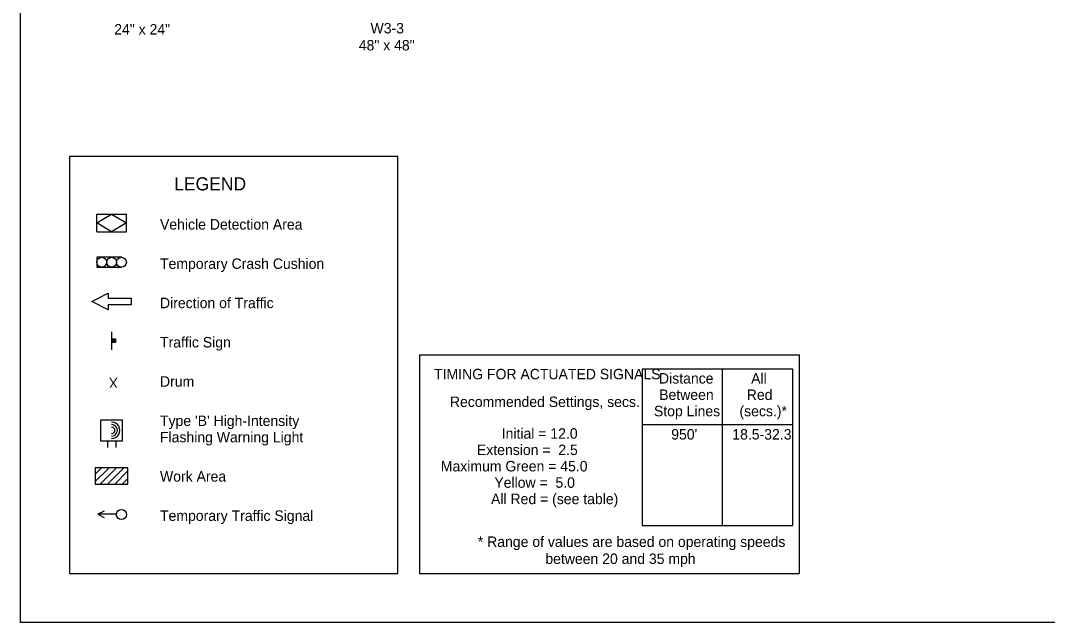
# Model space of a CAD drawing. Extents: x -2134934 to -2122394, y -2140205 to -2137036.
# Drawn here: x -2134934 to -2133366, y -2139046 to -2138126 of the extents above; entities that cross this region are included whole.
import ezdxf

# ---------------------------------------------------------------- set-up
doc = ezdxf.new("R2010")
doc.units = 0
for name, color, linetype in [('Barrier', 7, 'Continuous'), ('BridgeSuperStructureExisting', 7, 'Continuous'), ('Default', 7, 'Continuous'), ('dsnStdLabel', 7, 'Continuous'), ('dsnTextFinalPlan', 7, 'Continuous')]:
    doc.layers.add(name, color=color, linetype=linetype)

msp = doc.modelspace()

# ---------------------------------------------------------------- linework, layer by layer
at = {"layer": 'BridgeSuperStructureExisting'}
for p, q in [((-2134817.8, -2138449.1), (-2134817.8, -2138422.1)), ((-2134817.8, -2138422.1), (-2134772.8, -2138422.1)), ((-2134772.8, -2138449.1), (-2134772.8, -2138422.1)), ((-2134817.8, -2138449.1), (-2134772.8, -2138449.1)), ((-2134817.8, -2138488.1), (-2134817.8, -2138503.1)), ((-2134780.3, -2138488.1), (-2134817.8, -2138488.1)), ((-2134817.8, -2138503.1), (-2134780.3, -2138503.1)), ((-2134795.3, -2138601.9), (-2134795.3, -2138629.4)), ((-2134794.9, -2138618.4), (-2134794.9, -2138612.8)), ((-2134794.6, -2138612.8), (-2134794.6, -2138618.4)), ((-2134794.3, -2138618.4), (-2134794.3, -2138612.8)), ((-2134794.1, -2138612.8), (-2134794.1, -2138618.4)), ((-2134793.9, -2138618.4), (-2134793.9, -2138612.8)), ((-2134793.6, -2138612.8), (-2134793.6, -2138618.4)), ((-2134793.3, -2138618.4), (-2134793.3, -2138612.8)), ((-2134793, -2138612.8), (-2134793, -2138618.4)), ((-2134792.8, -2138618.4), (-2134792.8, -2138612.8)), ((-2134792.5, -2138612.8), (-2134792.5, -2138618.4)), ((-2134792.1, -2138618.4), (-2134792.1, -2138612.8)), ((-2134791.7, -2138612.8), (-2134791.7, -2138618.4)), ((-2134791.5, -2138618.4), (-2134791.5, -2138612.8)), ((-2134791.1, -2138612.8), (-2134791, -2138618.4)), ((-2134790.8, -2138618.4), (-2134790.8, -2138612.8)), ((-2134790.5, -2138612.8), (-2134790.5, -2138618.4)), ((-2134790.3, -2138618.4), (-2134790.3, -2138612.8)), ((-2134790, -2138612.8), (-2134790, -2138618.4)), ((-2134325, -2138636.9), (-2134325, -2138970.9)), ((-2134325, -2138636.9), (-2133745, -2138636.9)), ((-2133745, -2138636.9), (-2133745, -2138970.9)), ((-2134801.6, -2138768.8), (-2134801.6, -2138778.8)), ((-2134789.1, -2138768.8), (-2134789.1, -2138778.8)), ((-2134820.3, -2138830.5), (-2134799.3, -2138809.5)), ((-2134820.3, -2138819.2), (-2134810.6, -2138809.5)), ((-2134813, -2138834.5), (-2134788, -2138809.5)), ((-2134801.7, -2138834.5), (-2134776.7, -2138809.5)), ((-2134790.4, -2138834.5), (-2134770.3, -2138814.5)), ((-2134779, -2138834.5), (-2134770.3, -2138825.8)), ((-2134788.2, -2138880.6), (-2134816.1, -2138880.6)), ((-2134325, -2138970.9), (-2133745, -2138970.9))]:
    msp.add_line(p, q, dxfattribs=at)
for points in [[(-2134859.4, -2138970.9), (-2134357.9, -2138970.9), (-2134357.9, -2138334.3), (-2134859.4, -2138334.3)], [(-2134765.6, -2138550.6), (-2134765.6, -2138560.6), (-2134800.6, -2138560.6), (-2134800.6, -2138568.1), (-2134825.6, -2138555.6), (-2134800.6, -2138543.1), (-2134800.6, -2138550.6)], [(-2134795.2, -2138618.4), (-2134795.2, -2138612.7), (-2134789.6, -2138612.7), (-2134789.6, -2138618.4)], [(-2134811.6, -2138768.8), (-2134811.6, -2138736.3), (-2134779.1, -2138736.3), (-2134779.1, -2138768.8)], [(-2134820.3, -2138834.5), (-2134770.3, -2138834.5), (-2134770.3, -2138809.5), (-2134820.3, -2138809.5)]]:
    msp.add_lwpolyline(points, close=True, dxfattribs=at)
msp.add_lwpolyline([(-2134806.5, -2138875.7), (-2134816.5, -2138880.7), (-2134806.5, -2138885.7)], dxfattribs=at)
for centre, radius in [((-2134810.3, -2138495.6), 7.5), ((-2134810.3, -2138495.6), 7.5), ((-2134795.3, -2138495.6), 7.5), ((-2134795.3, -2138495.6), 7.5), ((-2134780.3, -2138495.6), 7.5), ((-2134780.3, -2138495.6), 7.5), ((-2134780.4, -2138880.9), 7.74)]:
    msp.add_circle(centre, radius, dxfattribs=at)
for radius in [12.5, 12.5, 8.75, 5]:
    msp.add_arc((-2134795.3, -2138752.5), radius, 269.4041, 90.5445, dxfattribs=at)
at = {"layer": 'Default'}
msp.add_lwpolyline([(-2134934.4, -2137035.9), (-2131799.4, -2137035.9), (-2131799.4, -2139045.9), (-2134934.4, -2139045.9)], close=True, dxfattribs=at)
at = {"layer": 'dsnStdLabel'}
for p, q in [((-2133985, -2138658.5), (-2133985, -2138897.6)), ((-2133985, -2138658.5), (-2133755, -2138658.5)), ((-2133862.6, -2138658.5), (-2133862.6, -2138897.6)), ((-2133755, -2138658.5), (-2133755, -2138897.6)), ((-2133985, -2138743.5), (-2133755, -2138743.5)), ((-2133985, -2138897.6), (-2133755, -2138897.6))]:
    msp.add_line(p, q, dxfattribs=at)
at = {"layer": 'dsnTextFinalPlan'}
msp.add_lwpolyline([(-2134817.8, -2138435.6), (-2134795.3, -2138422.1), (-2134772.8, -2138435.6), (-2134795.3, -2138449.1)], close=True, dxfattribs=at)

# ---------------------------------------------------------------- texts
at = {"layer": 'Barrier'}
for s, p in [('24" x 24"', (-2134791.3, -2138147.8)), ('W3-3', (-2134399.8, -2138146.1)), ('48" x 48"', (-2134417.7, -2138172.1))]:
    msp.add_text(s, height=16, dxfattribs=at).set_placement(p)
at = {"layer": 'BridgeSuperStructureExisting'}
msp.add_text('X', height=15, rotation=180, dxfattribs=at).set_placement((-2134785.9, -2138672.2))
at = {"layer": 'dsnStdLabel'}
for s, height, p in [('LEGEND', 20, (-2134699.8, -2138385.9)), ('Vehicle Detection Area', 16, (-2134721.4, -2138445.8)), ('Temporary Crash Cushion', 16, (-2134721.4, -2138505.8)), ('Direction of Traffic', 16, (-2134721.4, -2138565.8)), ('Traffic Sign', 16, (-2134721.4, -2138625.8)), ('Drum', 16, (-2134721.4, -2138685.8)), ('TIMING FOR ACTUATED SIGNALS', 16, (-2134302.7, -2138674.5)), ('Distance', 16, (-2133959.1, -2138681)), ('All', 16, (-2133818.3, -2138681)), ('Red', 16, (-2133825, -2138706)), ('Recommended Settings, secs.', 16, (-2134278.5, -2138716.8)), ('Between', 16, (-2133958.8, -2138706)), ('Stop Lines', 16, (-2133966.8, -2138731)), (' (secs.)*', 16, (-2133842.1, -2138731)), ("Type 'B' High-Intensity", 16, (-2134721.4, -2138745.8)), ('Initial = 12.0', 16, (-2134199.4, -2138765.2)), ("950'", 16, (-2133940.4, -2138766.5)), ('18.5-32.3', 16, (-2133847.1, -2138766.5)), ('Flashing Warning Light', 16, (-2134721.4, -2138770.8)), ('Extension =  2.5', 16, (-2134237.2, -2138790.2)), ('Maximum Green = 45.0', 16, (-2134292.4, -2138815.2)), ('Work Area', 16, (-2134721.4, -2138830.8)), ('Yellow =  5.0', 16, (-2134210.6, -2138840.2)), ('All Red = (see table)', 16, (-2134215.7, -2138865.2)), ('Temporary Traffic Signal', 16, (-2134721.4, -2138890.8)), ('* Range of values are based on operating speeds', 16, (-2134235.9, -2138930.6)), ('between 20 and 35 mph', 16, (-2134132.7, -2138956.6))]:
    msp.add_text(s, height=height, dxfattribs=at).set_placement(p)

doc.saveas('drawing.dxf')
